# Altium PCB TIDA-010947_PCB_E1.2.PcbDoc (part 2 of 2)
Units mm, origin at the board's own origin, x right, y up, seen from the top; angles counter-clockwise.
Board outline 34 x 34 mm, 4 copper layers (Top Layer, GND, PWR, Bottom Layer), stack 1.787 mm thick; 64 components, 51 nets, 201 pads, 60 vias.
Unrouted connection lines stored in the file: 1.
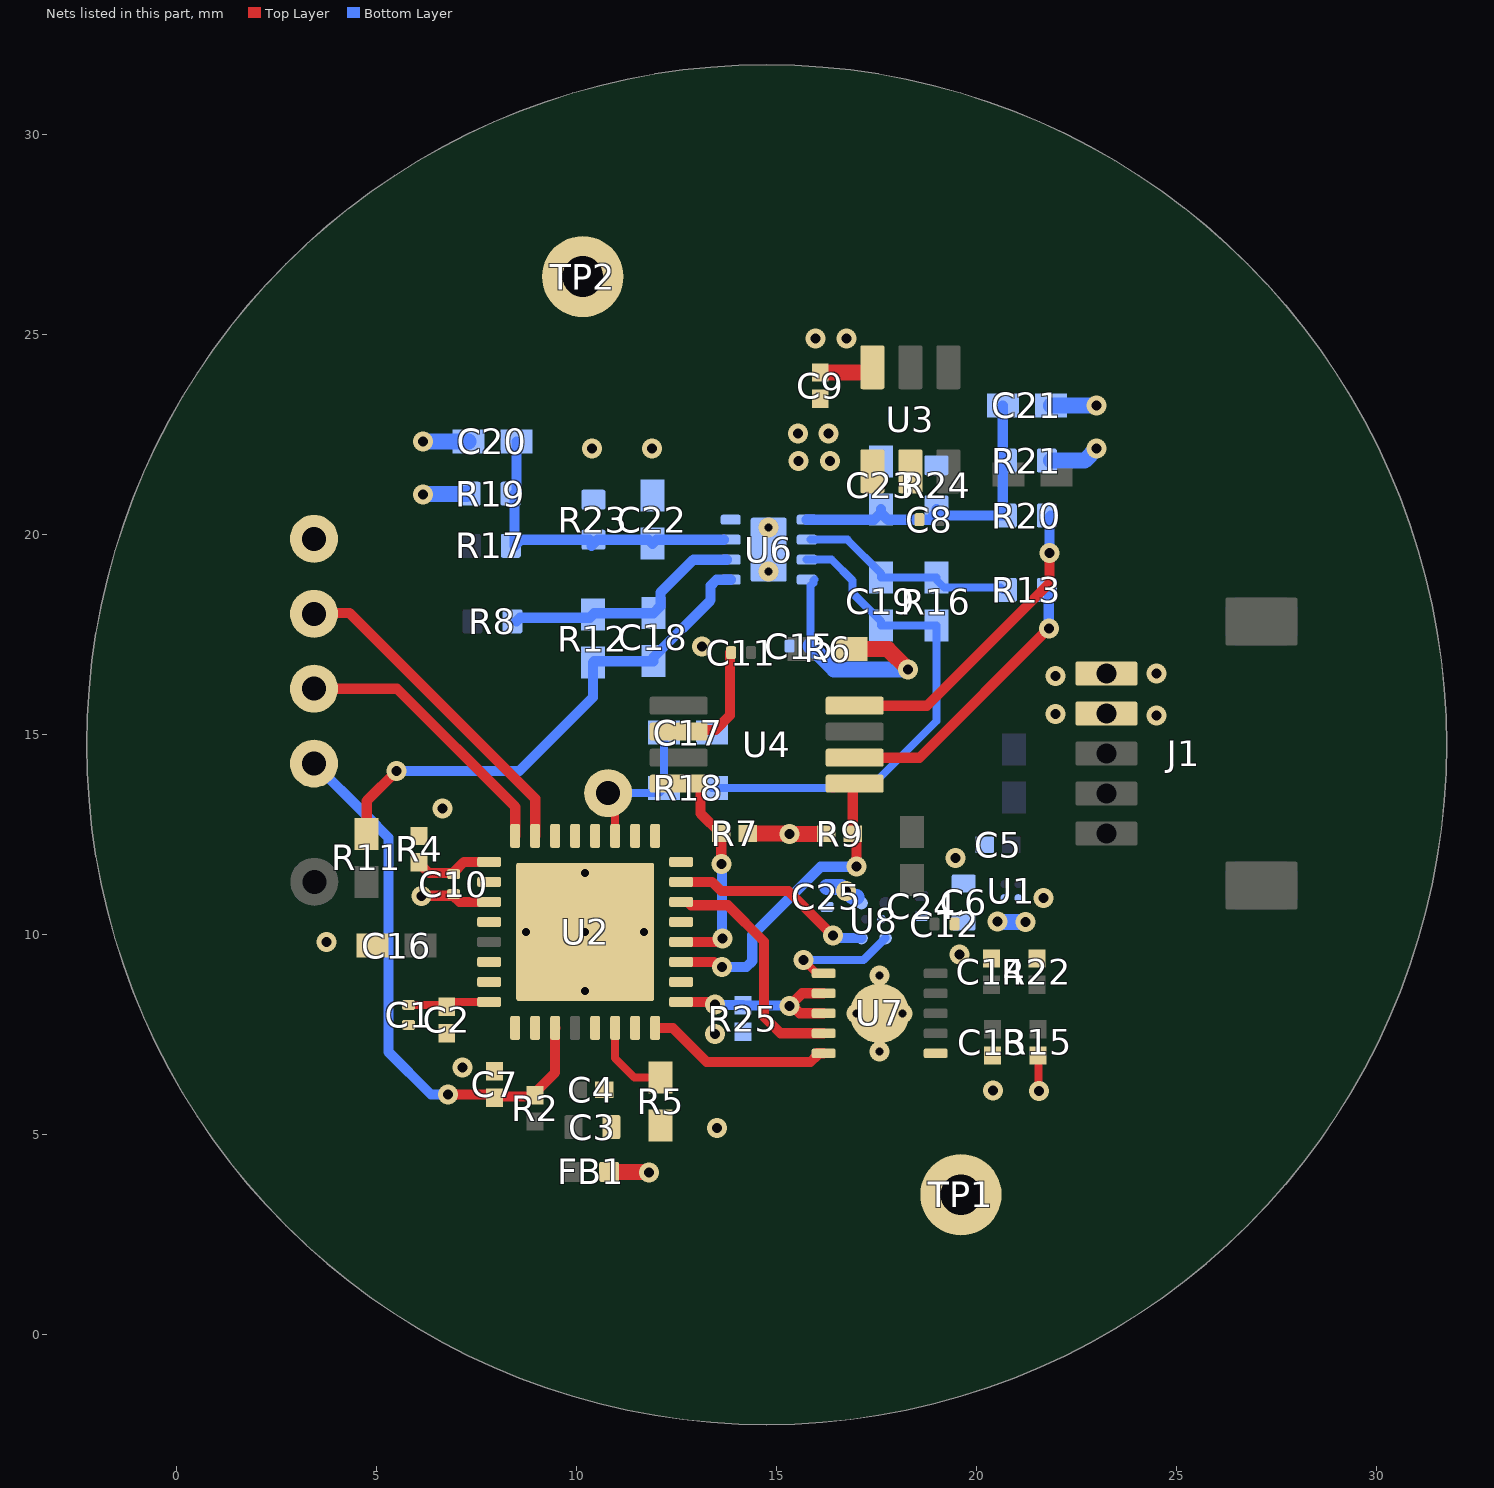
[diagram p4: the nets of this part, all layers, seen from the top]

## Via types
v1: diameter 0.5, hole 0.25, Top Layer to Bottom Layer, 49 vias
v2: diameter 0.5, hole 0.2, Top Layer to Bottom Layer, 11 vias

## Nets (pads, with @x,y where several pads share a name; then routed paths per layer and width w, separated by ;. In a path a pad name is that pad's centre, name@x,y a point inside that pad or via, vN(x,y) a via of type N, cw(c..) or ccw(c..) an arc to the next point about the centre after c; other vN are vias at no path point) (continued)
NetC18_1: C18.1 R11.1 R12.2 U6.1 | length 13
  Top Layer w0.254: R11.1@4.75,12.523 4.75,13.347 v1(5.497,14.094)
  Bottom Layer w0.254: v1(5.497,14.094) 8.566,14.094 10.404,15.931 R12.2@10.404,16.802 10.439,16.837 C18.1@11.919,16.837 11.919,16.937 13.347,18.365 13.347,18.726 13.496,18.875 U6.1@13.85,18.875
NetC18_2: C18.2 R8.2 R12.1 U6.2 | length 6.1
  Bottom Layer w0.254: R8.2@8.494,17.835 8.584,17.925 10.326,17.925 R12.1@10.404,18.002 10.439,18.037 C18.2@11.919,18.037 12.092,18.21 12.092,18.551 12.916,19.375 U6.2@13.75,19.375
NetC19_1: C19.1 R16.2 R18.1 U6.7 | length 12.8
  Bottom Layer w0.2: R18.1@13.387,13.674 17.325,13.674 18.99,15.339 R16.2@18.99,17.725 18.98,17.735 C19.1@17.605,17.735 17.605,17.835 16.895,18.545 16.895,18.855 16.375,19.375 U6.7@15.75,19.375
NetC19_2: C19.2 R13.2 R16.1 U6.6 | length 5.4
  Bottom Layer w0.2: U6.6@15.85,19.875 16.765,19.875 17.605,19.035 C19.2@17.605,18.935 18.98,18.935 R16.1@18.99,18.925 18.99,18.875 19.19,18.675 20.599,18.675 R13.2@20.652,18.622
NetC20_2: C20.2 C22.1 R17.2 R19.1 R23.2 U6.3 | length 8.2
  Bottom Layer w0.254: C20.2@8.494,22.333 8.494,21.07 8.448,21.024 8.448,19.728 8.452,19.724 8.604,19.875 10.317,19.875 R23.2@10.417,19.775 ; R23.2@10.366,19.724 R23.2@10.417,19.775 ; U6.3@13.675,19.875 11.994,19.875 C22.1@11.894,19.775 11.794,19.875 10.517,19.875 R23.2@10.417,19.775
NetC21_2: C21.2 C23.1 R20.2 R21.1 R24.2 U6.5 | length 8.1
  Bottom Layer w0.254: U6.5@15.75,20.375 17.432,20.375 C23.1@17.605,20.548 ; C23.1@17.605,20.637 C23.1@17.605,20.548 ; C21.2@20.652,23.235 20.652,21.853 20.652,20.479 19.148,20.479 18.99,20.637 18.99,20.548 18.817,20.375 17.778,20.375 C23.1@17.605,20.548
NetU7_1: U7.1 U8.3 | length 2.9
  Top Layer w0.2: v1(15.67,9.365) 15.67,9.359 15.994,9.035 U7.1@16.174,9.035
  Bottom Layer w0.2: v1(15.67,9.365) 17.17,9.365 U8.3@17.72,9.915
PA0: U2.1
PA1: U2.2
PA2: R5.2 U2.6 | length 2.1
  Top Layer w0.2: U2.6@10.962,7.67 10.954,7.663 10.954,6.913 11.443,6.424 R5.2@12.096,6.424
PA3: U2.7
PA4: U2.8 U7.5 | length 4.7
  Top Layer w0.254: U2.8@11.962,7.67 12.401,7.67 13.251,6.82 15.845,6.82 16.001,6.976 16.001,7.028 16.008,7.035 U7.5@16.174,7.035
PA5: R25.2 U2.9 U7.2 U7.3 | length 4.7
  Top Layer w0.254: U2.9@12.612,8.32 13.316,8.32 13.386,8.25 v1(13.453,8.25) ; U7.3@16.174,8.035 15.574,8.035 15.39,8.219 v1(15.324,8.219) 15.639,8.535 U7.2@16.174,8.535
  Bottom Layer w0.254: v1(13.453,8.25) 13.461,8.242 14.153,8.242 14.168,8.227 15.316,8.227 v1(15.324,8.219)
PA6: U2.10
PA7: R9.1 U2.11 U4.5 | length 8.6
  Top Layer w0.254: U2.11@12.612,9.32 13.435,9.32 13.564,9.191 v1(13.63,9.191) ; U4.5@16.401,13.677 16.499,13.775 U4.5@16.95,13.775 16.9,13.725 R9.1@16.9,12.523 16.915,12.523 16.998,12.44 v1(16.998,11.701)
  Bottom Layer w0.254: v1(13.63,9.191) 14.241,9.191 14.389,9.34 14.389,9.989 16.102,11.701 v1(16.998,11.701)
PA8: R7.1 U2.12 U4.4 | length 5.5
  Top Layer w0.254: U4.4@12.55,13.775 13.001,13.775 13.099,13.677 13.099,13.027 13.595,12.53 R7.1@13.615,12.53 v1(13.615,11.765) ; U2.12@12.785,9.82 13.503,9.82 13.583,9.9 v1(13.65,9.9)
  Bottom Layer w0.254: v1(13.615,11.765) 13.633,11.748 13.633,9.918 v1(13.65,9.9)
PA9: U2.13
PA10: U2.14 U7.4 | length 5.9
  Top Layer w0.254: U2.14@12.785,10.818 12.865,10.738 13.776,10.738 14.683,9.831 14.683,7.947 15.095,7.535 U7.4@16.174,7.535
PA11: U2.15 U8.4 | length 4.9
  Top Layer w0.254: U2.15@12.785,11.32 13.386,11.32 13.614,11.092 15.288,11.092 v1(16.405,9.975)
  Bottom Layer w0.254: v1(16.405,9.975) 16.471,9.975 16.532,9.915 U8.4@17.12,9.915
PA12: U2.16
PA13: U2.17
PA14: U2.18
PA15: C17.1 pad.8@10.784,13.541 R18.2 U2.19 | length 4
  Top Layer w0.2: pad.8@10.784,13.541 10.962,13.363 U2.19@10.962,12.47
  Bottom Layer w0.2: pad.8@10.784,13.545 12.058,13.545 R18.2@12.187,13.674 C17.1@12.187,15.054
PA16: U2.20
PA17: U2.21
PA18: U2.22
PA19: pad.8@3.432,18.024 U2.23 | length 8.4
  Top Layer w0.254: pad.8@3.441,18.035 3.458,18.046 4.317,18.046 8.962,13.401 U2.23@8.962,12.47
PA20: pad.8@3.432,16.152 U2.24 | length 7.3
  Top Layer w0.254: pad.8@3.653,15.905 3.653,15.917 3.441,16.13 3.461,16.151 5.506,16.151 8.462,13.196 U2.24@8.462,12.47
PA21: C10.2 R4.2 U2.25 | length 2
  Top Layer w0.254: R4.2@6.061,11.808 6.061,11.788 6.304,11.545 6.923,11.545 6.923,11.565 7.178,11.82 U2.25@7.812,11.82
PA22: U2.26
PA23: C9.1 C10.1 C20.1 C21.1 R19.2 R21.2 U2.27 U3.6 | length 7.8
  Top Layer w0.254: v1(6.121,10.965) 6.131,10.975 6.913,10.975 6.923,10.985 6.923,10.965 7.068,10.82 U2.27@7.812,10.82
  Top Layer w0.4: C9.1@16.09,24.056 17.29,24.056 17.39,24.156 U3.6@17.39,24.187
  Bottom Layer w0.4: v1(6.152,21.01) 6.159,21.017 7.241,21.017 R19.2@7.248,21.024 ; v1(6.152,22.333) C20.1@7.294,22.333 ; R21.2@21.852,21.853 22.695,21.853 v1(23,22.158) ; C21.1@21.852,23.235 21.853,23.236 v1(23,23.237) v1(23,23.237)
  other v1: 15.97,24.909 16.749,24.909
PA24: U2.28
PA26: U2.30
PA27: U2.31
R\S\T\: C7.1 pad.8@3.432,14.279 R2.1 U2.3 | length 13.8
  Top Layer w0.254: v1(6.776,6.004) 7.872,6.004 C7.1@7.948,5.929 7.978,5.959 8.93,5.959 R2.1@8.96,5.989 ; R2.1@9.043,6.139 9.46,6.555 9.46,7.668 U2.3@9.462,7.67
  Bottom Layer w0.254: pad.8@3.441,14.279 4.735,12.984 4.738,12.984 5.291,12.432 5.291,7.071 6.357,6.004 v1(6.776,6.004)
SIN_N: R13.1 U4.6 | length 7.2
  Top Layer w0.254: U4.6@16.95,14.425 18.569,14.425 v1(21.802,17.658)
  Bottom Layer w0.254: v1(21.802,17.658) 21.802,18.572 R13.1@21.852,18.622
SIN_P: R20.1 U4.8 | length 7.8
  Top Layer w0.254: U4.8@16.95,15.725 18.759,15.725 21.816,18.782 v1(21.816,19.544)
  Bottom Layer w0.254: v1(21.816,19.544) 21.816,20.442 R20.1@21.852,20.479
TPAD: C1.2 C2.1 C3.2 C4.1 C5.2 C6.1 C7.2 C8.1 C9.2 C11.1 C12.1 C13.1 C14.2 C15.1 C16.2 C17.2 C22.2 C23.2 C24.1 C25.1 J1.4 J1.5 pad.8@3.432,19.897 pad.9 pad.10 R4.1 R5.1 R22.1 R23.1 R24.1 R25.1 TP1.1 TP2.1 U1.B2 U2.5 U2.33 U3.1 U3.2 U4.2 U6.4 U6.9@14.8,19.625 U7.6 U7.11 U8.2 | length 3
  Top Layer w0.254: U4.2@12.55,15.075 12.59,15.115 13.462,15.115 13.83,15.483 C11.1@13.83,17.052
  other v1: 13.51,5.171 20.413,6.103 7.149,6.675 13.461,7.52 19.576,9.506 3.75,9.82 21.669,10.913 19.475,11.923 6.644,13.153 24.5,15.484 21.965,15.514 21.965,16.473 24.5,16.53 13.135,17.202 15.544,21.845 16.329,21.845 10.387,22.159 11.881,22.159 15.537,22.537 16.3,22.532
  other v2: 17.574,7.085 16.999,8.035 18.149,8.035 10.212,8.595 17.574,8.985 8.737,10.07 10.212,10.07 11.687,10.07 10.212,11.545 14.8,19.075 14.8,20.175
VCORE: C1.1 C2.2 U2.32 | length 2.1
  Top Layer w0.2: C1.1@5.797,8.246 6.705,8.246 C2.2@6.749,8.201 6.749,8.21 6.859,8.32 U2.32@7.812,8.32
VDD_3V3: C6.2 C15.2 C25.2 FB1.2 R6.1 R7.2 R9.2 R15.2 U1.A2 U6.8 U8.6 | length 11.4
  Top Layer w0.2: R15.2@21.53,6.98 21.542,6.968 21.542,6.103 v1(21.554,6.09)
  Top Layer w0.4: FB1.2@10.812,4.07 10.818,4.064 11.795,4.064 v1(11.802,4.058) ; R7.2@14.275,12.53 14.278,12.527 15.32,12.527 v1(15.324,12.523) R9.2@16.24,12.523 ; R6.1@16.87,17.137 17.776,17.137 v1(18.283,16.63)
  Bottom Layer w0.2: C15.2@15.85,17.218 15.85,18.733 15.915,18.798 15.915,18.852 U6.8@15.939,18.875
  Bottom Layer w0.4: C15.2@15.85,17.218 16.438,16.63 v1(18.283,16.63) ; C25.2@16.255,11.195 16.605,11.195 16.708,11.092 v1(16.735,11.092) 16.762,11.092 16.914,10.94 16.995,10.94 ; v1(20.514,10.325) 20.516,10.323 21.217,10.323 v1(21.22,10.32)
pads on no net: J1.MP1 J1.MP2 U3.5 U6.9@14.8,19.175 U6.9@14.8,20.075 U7.7

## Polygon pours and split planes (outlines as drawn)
TPAD on Bottom Layer "BOTTOM_LAYER_TPAD_P050" (solid, pour order 50): -2.25,31.75 31.75,31.75 31.75,-2.25 -2.25,-2.25
VDD_3V3 on Bottom Layer "BOTTOM_LAYER_VDD_3V3_P014" (solid, pour order 14): 20.514,11.018 20.849,11.018 20.849,10.63 20.849,10.02 19.552,10.02 19.502,10.07 19.502,10.808 20.444,10.808 20.514,10.878
NetC5_1 on Bottom Layer "BOTTOM_LAYER_NETC5_1_P017" (solid, pour order 17): 20.514,13.93 20.514,11.162 21.284,11.162 21.284,13.93
TPAD on Top Layer "TOP_LAYER_TPAD_P045" (solid, pour order 45): -2.25,31.75 31.75,31.75 31.75,-2.25 -2.25,-2.25
MCU_3V3 on Top Layer "TOP_LAYER_MCU_3V3_P029" (solid, pour order 29): 10.362,6.289 10.362,3.795 8.877,3.795 8.667,4.006 8.667,5.654 9.18,5.654 9.815,6.289
NetC8_2 on Top Layer "TOP_LAYER_NETC8_2_P015" (solid, pour order 15): 18.99,24.75 18.99,20.889 18.88,20.779 18.88,20.205 19.994,20.205 20.989,21.2 21.234,21.2 21.234,24.638 21.122,24.75
5V on Top Layer "TOP_LAYER_5V_P016" (solid, pour order 16): 22.472,14.208 25.864,14.208 25.864,21.805 21.602,21.805 21.602,21.249 21.554,21.2 25.056,21.2 25.056,15 22.472,15
PA23 on Top Layer "TOP_LAYER_PA23_P023" (solid, pour order 23): 15.614,25.18 15.614,23.824 16.964,23.824 17.085,23.704 17.69,23.704 17.69,25.12 17.631,25.18
TPAD on PWR "PWR_TPAD_P047" (solid, pour order 47): -2.25,31.75 31.75,31.75 31.75,-2.25 -2.25,-2.25
VDD_3V3 on PWR "PWR_VDD_3V3_P044" (solid, pour order 44): 14.382,12.699 15.97,11.111 17.061,10.02 20.772,10.02 20.772,12.736 20.728,12.78
VDD_3V3 on PWR "PWR_VDD_3V3_P018" (solid, pour order 18): 20.849,10.02 19.552,10.02 19.552,15.905 19.091,16.366 17.896,16.366 17.896,17.047 18.051,17.202 20.795,17.202 20.795,10.075
PA23 on PWR "PWR_PA23_P022" (solid, pour order 22): 22.296,21.853 22.313,21.837 24,21.837 24,25 23.82,25.18 6.871,25.18 5.565,23.874 5.565,10.925 6.047,10.443 6.776,10.443 6.776,22.676 7.804,23.704 21.837,23.704 22.296,23.244
VDD_3V3 on PWR "PWR_VDD_3V3_P032" (solid, pour order 32): 20.135,10.713 21.815,10.713 21.965,10.563 21.94,10.538 21.94,5.274 13.655,5.274 11.881,3.5 11.398,3.5 11.398,4.654 13.135,6.39 19.527,6.39 20.135,6.998
TPAD on GND "GND_TPAD_P046" (solid, pour order 46): -2.25,31.75 31.75,31.75 31.75,-2.25 -2.25,-2.25

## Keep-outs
Keep-Out Layer:
  text ".Layer_Name" at 14.656,-21.806 h0.9

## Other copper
Top Layer:
  text ".Layer_Name" at 14.656,-21.806 h0.9
Bottom Layer:
  text ".Layer_Name" at 14.656,-21.806 h0.9

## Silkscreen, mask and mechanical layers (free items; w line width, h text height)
Top Overlay:
  lines w0.254: 4.251,13.416 2.5,13.416 2.5,20.834 4.263,20.834 4.263,13.429
  text "4-GND / 3-DIO / 2-CLK / 1-RST" at -1,16.537 h1.2
  text "5-GND / 4-GND / 3-5V / 2-B / 1-A" at 26.243,5.483 h1.2
  text ".Layer_Name" at 14.656,-21.806 h0.9
Bottom Overlay:
  text "4-GND / 3-DIO / 2-CLK / 1-RST" at 2.25,16.473 h1.2
  text "5-GND / 4-GND / 3-5V / 2-B / 1-A" at 27.874,5.468 h1.2
  text ".Layer_Name" at 14.656,-21.806 h0.9
Top Paste:
  text ".Layer_Name" at 14.656,-21.806 h0.9
Bottom Paste:
  text ".Layer_Name" at 14.656,-21.806 h0.9
Top Solder:
  text ".Layer_Name" at 14.656,-21.806 h0.9
  text ".Layer_Name" at 14.656,-21.806 h0.9
Bottom Solder:
  text ".Layer_Name" at 14.656,-21.806 h0.9
Drill Guide:
  text ".Layer_Name" at 14.656,-21.806 h0.9
M1 Board Outline:
  circle w0.254: c29.5,14.75 r1
  circle w0.254: c0,14.75 r1
  circle w0.254: c4.32,4.32 r1.2
  circle w0.254: c25.18,25.18 r1.2
  circle w0.254: c14.75,29.5 r1
  circle w0.254: c4.32,25.18 r1.2
  circle w0.254: c14.75,0 r1
  circle w0.254: c25.18,4.32 r1.2
  circle w0.254: c14.75,14.75 r17
  text ".Layer_Name" at 14.656,-21.806 h0.9
M2 Board Dimensions:
  rectangle: 0,-6.985 3.175,-3.81
  rectangle: 3.175,-10.16 12.7,-6.985
  lines w0.178: 0,-6.985 25.4,-6.985 ; 3.175,-10.16 3.175,-3.81 ; 6.35,-10.16 6.35,-3.81 ; 12.7,-10.16 12.7,-3.81 ; 19.05,-10.16 19.05,-3.81 ; 0,-10.16 25.4,-10.16 25.4,-3.81 0,-3.81 0,-10.16
  text ".Layer_Name" at 14.656,-21.806 h0.9
M3 3D STEP Top:
  text ".Layer_Name" at 14.656,-21.806 h0.9
M4 3D STEP Bottom:
  text ".Layer_Name" at 14.656,-21.806 h0.9
M5 Assembly Top:
  lines w0.254: -7.417,-23.626 160.223,-23.626 ; -7.417,-18.462 160.274,-18.462 ; -7.417,-13.297 -7.417,-28.791 94.31,-28.791 160.274,-28.791 160.274,-13.297 -7.404,-13.297 -7.404,-28.791 32.614,-28.791 ; 55.194,-28.791 55.194,-13.297 ; 87.376,-18.462 87.376,-13.297 ; 108.712,-18.462 108.712,-13.297 ; 124.511,-28.956 124.511,-23.804
  text "COMPONENTS MARKED 'DNP' SHOULD NOT BE POPULATED." at 29.299,-8.09 h1.02
  text "ASSEMBLY VARIANT:" at 29.286,-11.024 h1.02
  text ".VariantName" at 55.601,-11.024 h1.02
  text "PCB VIEWED FROM TOP SIDE" at -5.804,-16.654 h0.9
  text "BOARD #:" at 57.099,-16.654 h0.9
  text ".PRJ_Number" at 70.955,-16.654 h0.9
  text "REV:" at 92.405,-16.654 h0.9
  text ".PCB_Rev" at 99.809,-16.654 h0.9
  text "SVN REV:" at 113.69,-16.654 h0.9
  text ".VersionControl_RevNumber" at 126.543,-16.654 h0.9
  text "TID #:" at 57.099,-21.819 h0.9
  text ".TID" at 70.955,-21.819 h0.9
  text "PLOT NAME =" at -5.804,-27.034 h0.9
  text ".plot_File_Name" at 14.656,-27.034 h0.9
  text "GENERATED    :" at 57.15,-27.034 h0.9
  text ".Print_Date" at 79.235,-27.034 h0.9
  text ".Print_Time" at 97.752,-27.034 h0.9
  text "TEXAS INSTRUMENTS" at 129.87,-27.034 h0.9
M6 Assembly Bottom:
  lines w0.254: -7.429,-18.474 160.261,-18.474 ; -7.379,-23.639 160.261,-23.639 ; 28.334,-28.969 28.334,-23.817 ; 44.133,-18.474 44.133,-13.31 ; 65.468,-18.474 65.468,-13.31 ; 97.65,-28.804 97.65,-13.31 ; 120.231,-28.804 160.249,-28.804 160.249,-13.31 -7.429,-13.31 -7.429,-28.804 58.534,-28.804 160.261,-28.804 160.261,-13.31
  text "COMPONENTS MARKED 'DNP' SHOULD NOT BE POPULATED." at 154.991,-8.077 h1.02
  text ".VariantName" at 128.473,-11.024 h1.02
  text "ASSEMBLY VARIANT:" at 154.864,-11.024 h1.02
  text ".VersionControl_RevNumber" at 26.302,-16.667 h0.9
  text "SVN REV:" at 39.154,-16.667 h0.9
  text ".PCB_Rev" at 53.035,-16.667 h0.9
  text "REV:" at 60.439,-16.667 h0.9
  text ".PRJ_Number" at 81.89,-16.667 h0.9
  text "BOARD #:" at 95.745,-16.667 h0.9
  text "PCB VIEWED FROM BOTTOM SIDE" at 158.648,-16.667 h0.9
  text ".TID" at 81.89,-21.831 h0.9
  text "TID #:" at 95.745,-21.831 h0.9
  text "TEXAS INSTRUMENTS" at 22.974,-27.047 h0.9
  text ".Print_Time" at 55.093,-27.047 h0.9
  text ".Print_Date" at 73.609,-27.047 h0.9
  text "GENERATED    :" at 95.694,-27.047 h0.9
  text ".plot_File_Name" at 138.189,-27.047 h0.9
  text "PLOT NAME =" at 158.648,-27.047 h0.9
M9 Title Sheet:
  drawing of 57 lines, arcs and shapes, not listed
  text "1" at 18.792,204.127 h1.78
  text "2" at 82.182,204.127 h1.78
  text "3" at 145.411,204.127 h1.78
  text "4" at 209.08,204.127 h1.78
  text "5" at 272.555,204.127 h1.78
  text "6" at 336.182,204.127 h1.78
  text "A" at -10.579,175.095 h1.78
  text "A" at 365.341,175.095 h1.78
  text "B" at -10.579,114.643 h1.78
  text "B" at 365.341,114.643 h1.78
  text "C" at -10.579,54.318 h1.78
  text "C" at 365.341,54.318 h1.78
  text "PROJECT TITLE:" at 288.125,7.048 h1.14
  text ".PRJ_Title" at 289.395,3.662 h1.78
  text "DESIGNED FOR:" at 288.125,-0.597 h1.14
  text ".PRJ_Customer" at 289.395,-4.153 h1.78
  text "D" at -10.579,-5.88 h1.78
  text "D" at 365.341,-5.88 h1.78
  text "FILE NAME:" at 288.125,-8.217 h1.14
  text ".PCB_File_Name_No_Path" at 289.395,-11.265 h1.78
  text "Texas Instruments (TI) and/or its licensors do not warrant the accuracy or completeness of this specification" at 161.9,-15.376 h1.14
  text "ENGINEER:" at 288.125,-15.583 h1.14
  text "LAYOUT BY:" at 326.352,-15.583 h1.14
  text "or any information contained therein. TI and/or its licensors do not warrant that this design will meet" at 160.757,-18.237 h1.14
  text ".PRJ_Engineer" at 289.395,-19.52 h1.78
  text ".PCB_Layout" at 327.635,-19.52 h1.78
  text "the specifications, will be suitable for your application or fit for any particular purpose, or will operate in" at 160.757,-21.099 h1.14
  text ".Layer_Name" at 14.656,-21.806 h0.9
  text "ALTIUM DESIGNER VERSION:" at 326.352,-23.457 h1.14
  text "an implementation. TI and/or its licensors do not warrant that the design is production worthy. You should" at 160.757,-23.961 h1.14
  text "completely validate and test your design implementation to confirm the system functionality for your application." at 161.9,-26.822 h1.14
  text ".print_Scale" at 289.395,-26.843 h1.78
  text ".Application_BuildNumber" at 327.635,-26.843 h1.78
  text "1" at 18.792,-32.093 h1.78
  text "2" at 82.182,-32.093 h1.78
  text "3" at 145.411,-32.093 h1.78
  text "4" at 209.08,-32.093 h1.78
  text "5" at 272.555,-32.093 h1.78
  text "6" at 336.182,-32.093 h1.78
M10 Fab Notes:
  drawing of 189 lines, arcs and shapes, not listed
  text "DESIGN INFORMATION" at 314.503,161.447 h0.9
  text "MIN. TRACK WIDTH:" at 298.131,158.091 h0.9
  text "8" at 325.976,158.091 h0.9
  text "MIL" at 329.907,158.091 h0.9
  text "7.874" at 321.75,155 h0.9
  text "MIN. CLEARANCE:" at 298.131,154.938 h0.9
  text "MIL" at 329.907,154.938 h0.9
  text "MIN. VIA PAD SIZE:" at 298.131,151.785 h0.9
  text "24" at 325.214,151.785 h0.9
  text "MIL" at 329.907,151.785 h0.9
  text "0.05mm (2MIL)" at 315.784,148.486 h0.9
  text "MINIMUM ANNULAR RING" at 289.769,148.277 h0.9
  text "EXTERNAL" at 333.768,148.277 h0.9
  text "PER" at 294.849,145.48 h0.9
  text "IPC-D-275 CLASS 2 LEVEL C" at 300.437,145.48 h0.9
  text "MIL, HOLES" at 338.238,142.928 h0.9
  text "+/-" at 328.27,142.709 h0.9
  text "+/-" at 349.961,142.709 h0.9
  text "REGISTRATION TOLERANCES:" at 289.769,142.682 h0.9
  text "METAL" at 320.243,142.682 h0.9
  text "5" at 334.879,142.683 h0.9
  text "3" at 356.037,142.683 h0.9
  text "MIL" at 358.99,142.682 h0.9
  text "HOLE SIZE TOLERANCE (UNLESS OTHERWISE SPECIFIED):" at 289.769,140.185 h0.9
  text "+/-" at 349.961,140.112 h0.9
  text "3" at 356.037,140.085 h0.9
  text "MIL" at 358.99,140.085 h0.9
  text "MATERIAL:" at 287.87,136.589 h0.9
  text "FR-4 High Tg" at 312.926,133.324 h0.9
  text "X" at 309.257,133.122 h0.9
  text "FR-4" at 298.563,133.007 h0.9
  text "OTHER" at 336.358,133.007 h0.9
  text "62 MIL (1.6mm) +/-10%" at 306.694,129.374 h0.9
  text "X" at 303.643,129.312 h0.9
  text "THICKNESS:" at 289.769,129.165 h0.9
  text "OTHER" at 339.33,129.165 h0.9
  text "TOLERANCE:" at 289.769,125.652 h0.9
  text "X" at 311.314,125.652 h0.9
  text "ANSI IPC-6012 TYPE 3 CLASS 2" at 315.836,125.652 h0.9
  text "OTHER +/-" at 315.835,121.989 h0.9
  text "BOW & TWIST:" at 289.769,118.302 h0.9
  text "X" at 311.314,118.302 h0.9
  text "ANSI IPC-6012 TYPE 3 CLASS 2" at 315.836,118.302 h0.9
  text "OTHER +/-" at 315.835,114.576 h0.9
  text "DRILLING:" at 287.87,111.258 h0.9
  text "NC_DRILL FILES" at 332.599,108.586 h0.9
  text "REFERENCE:" at 289.769,108.486 h0.9
  text "X" at 306.463,108.484 h0.9
  text "AS SHOWN" at 310.984,108.486 h0.9
  text "X" at 329.348,108.486 h0.9
  text "OTHER" at 340.168,104.873 h0.9
  text "PTH COPPER THICKNESS:" at 289.761,104.783 h0.9
  text "X" at 318.697,104.783 h0.9
  text "20-30 um" at 321.948,104.783 h0.9
  text "BOARD FINISH:" at 287.87,101.034 h0.9
  text "SILKSCREEN:" at 291.812,98.237 h0.9
  text "X" at 316.14,98.237 h0.9
  text "TOP" at 319.112,98.237 h0.9
  text "X" at 329.094,98.237 h0.9
  text "BOTTOM" at 332.091,98.237 h0.9
  text "SILKSCREEN COLOR:" at 291.812,94.295 h0.9
  text "X" at 316.115,94.295 h0.9
  text "WHITE" at 319.112,94.295 h0.9
  text "OTHER" at 332.091,94.295 h0.9
  text "X" at 319.442,90.652 h0.9
  text "GREEN" at 322.439,90.652 h0.9
  text "OTHER" at 338.136,90.652 h0.9
  text "SOLDER RESIST COLOR:" at 291.812,90.477 h0.9
  text "X" at 319.442,86.734 h0.9
  text "MATTE" at 322.439,86.734 h0.9
  text "SEMI-GLOSS" at 338.125,86.717 h0.9
  text "IMMERSION GOLD (ENIG)" at 314.819,82.345 h0.9
  text "ENEPIG" at 348.793,82.162 h0.9
  text "SURFACE FINISH:" at 287.87,82.136 h0.9
  text "X" at 310.298,82.136 h0.9
  text "IMM. TIN/SILVER OR EQUIV" at 296.24,78.649 h0.9
  text "OTHER" at 332.599,78.549 h0.9
  text "ARRAY/PANEL:" at 287.87,74.602 h0.9
  text "CUT AND TRIM PER M1 BOARD OUTLINE" at 314.819,74.393 h0.9
  text "N.C. ROUTE" at 314.819,70.94 h0.9
  text "X" at 332.295,70.94 h0.9
  text "V. SCORE" at 336.816,70.94 h0.9
  text "CERTIFICATION:" at 287.87,67.66 h0.9
  text "MATERIALS AND WORKMANSHIP FOR ALL PCBS" at 306.285,67.66 h0.9
  text "TO MEET OR EXCEED THE REQUIREMENTS OF:" at 306.285,65.271 h0.9
  text "X" at 297.078,62.003 h0.9
  text "ANSI IPC-A-600F CLASS ->" at 300.329,62.003 h0.9
  text "X" at 342.188,62.003 h0.9
  text "2" at 344.982,62.003 h0.9
  text "1" at 336.981,61.965 h0.9
  text "3" at 353.973,61.965 h0.9
  text "X" at 317.702,58.252 h0.9
  text "RoHS" at 320.953,58.252 h0.9
  text "OTHER" at 337.321,58.252 h0.9
  text "PER ORDER" at 347.407,58.252 h0.9
  text "ALL BOARDS MUST MEET OR EXCEED UL94-V0 REQUIREMENTS." at 288.569,54.345 h0.9
  text "PCB MUST BEAR THE UL94V-0 UL REGISTERED MATERIAL ID NUMBER" at 288.569,51.397 h0.9
  text "ADDITIONAL REQUIREMENTS:" at 287.87,47.094 h0.9
  text "MICROSECTION:" at 289.769,44.373 h0.9
  text "YES" at 312.775,44.373 h0.9
  text "REQUIRED" at 334.657,40.707 h0.9
  text "BARE BOARD ELEC. TEST:" at 289.769,40.634 h0.9
  text "NONE" at 322.935,40.634 h0.9
  text "X" at 331.66,40.634 h0.9
  text "PER ORDER" at 349.693,40.634 h0.9
  text "XX MIL VIAS REQUIRE NON-CONDUCTIVE FILL AND PLANARIZE" at 294.04,35.428 h1.5
  text "XX MIL VIAS REQUIRE CONDUCTIVE FILL AND PLANARIZE" at 294.243,32.787 h0.9
  text "OUTER XX MIL TRACES REQUIRE 50 OHM SINGLE-ENDED IMPEDANCE" at 294.218,28.637 h1.47
  text "LAYER 2 & 3 (INNER LAYERS) XX MIL WIDE, XX MIL SPACE / TRACES REQUIRE 100 OHM DIFFERENTIAL IMPEDANCE" at 294.015,22.65 h0.9
  text ".Layer_Name" at 14.656,-21.806 h0.9
M11 Gerber Information:
  lines w0.254: -7.417,-23.626 160.223,-23.626 ; -7.417,-18.462 160.274,-18.462 ; -7.417,-13.297 -7.417,-28.791 94.31,-28.791 160.274,-28.791 160.274,-13.297 -7.404,-13.297 -7.404,-28.791 32.614,-28.791 ; 55.194,-28.791 55.194,-13.297 ; 87.376,-18.462 87.376,-13.297 ; 108.712,-18.462 108.712,-13.297 ; 124.511,-28.956 124.511,-23.804
  text "ALL ARTWORK VIEWED FROM TOP SIDE" at -5.804,-16.654 h0.9
  text "BOARD #:" at 57.099,-16.654 h0.9
  text ".PRJ_Number" at 70.955,-16.654 h0.9
  text "REV:" at 92.405,-16.654 h0.9
  text ".PCB_Rev" at 99.809,-16.654 h0.9
  text "SVN REV:" at 113.69,-16.654 h0.9
  text ".VersionControl_RevNumber" at 126.543,-16.654 h0.9
  text "LAYER NAME =" at -5.804,-21.806 h0.9
  text "TID #:" at 57.099,-21.819 h0.9
  text ".TID" at 70.955,-21.819 h0.9
  text "PLOT NAME =" at -5.804,-27.034 h0.9
  text ".plot_File_Name" at 14.656,-27.034 h0.9
  text "GENERATED    :" at 57.15,-27.034 h0.9
  text ".Print_Date" at 79.235,-27.034 h0.9
  text ".Print_Time" at 97.752,-27.034 h0.9
  text "TEXAS INSTRUMENTS" at 129.87,-27.034 h0.9
M12 Stackup:
  drawing of 196 lines, arcs and shapes, not listed
  text "Layer" at 248.707,200.785 h1.02
  text "Name" at 252.958,200.785 h1.02
  text "Material" at 261.181,200.785 h1.02
  text "Thickness" at 268.57,200.785 h1.02
  text "Constant" at 274.639,200.785 h1.02
  text "Board Layer Stack" at 280.256,200.785 h1.02
  text "Top Overlay" at 252.958,198.753 h1.02
  text "Top Solder" at 252.958,196.721 h1.02
  text "Solder Resist" at 261.181,196.721 h1.02
  text "0.40mil" at 268.57,196.721 h1.02
  text "3.5" at 274.639,196.721 h1.02
  text "1" at 248.707,194.689 h1.02
  text "Top Layer" at 252.958,194.689 h1.02
  text "1.40mil" at 268.57,194.689 h1.02
  text "Dielectric 1" at 252.958,192.657 h1.02
  text "PP-006" at 261.181,192.657 h1.02
  text "2.80mil" at 268.569,192.657 h1.02
  text "4.1" at 274.639,192.657 h1.02
  text "2" at 248.706,190.625 h1.02
  text "GND" at 252.958,190.625 h1.02
  text "CF-004" at 261.181,190.625 h1.02
  text "1.38mil" at 268.57,190.625 h1.02
  text "Dielectric1" at 252.958,188.593 h1.02
  text "FR-4 High Tg" at 261.181,188.593 h1.02
  text "59.20mil" at 268.57,188.593 h1.02
  text "4.8" at 274.639,188.593 h1.02
  text "3" at 248.707,186.561 h1.02
  text "PWR" at 252.958,186.561 h1.02
  text "CF-004" at 261.181,186.561 h1.02
  text "1.38mil" at 268.57,186.561 h1.02
  text "Dielectric 2" at 252.958,184.529 h1.02
  text "PP-006" at 261.181,184.529 h1.02
  text "2.80mil" at 268.569,184.529 h1.02
  text "4.1" at 274.639,184.529 h1.02
  text "4" at 248.707,182.497 h1.02
  text "Bottom Layer" at 252.958,182.497 h1.02
  text "1.40mil" at 268.57,182.497 h1.02
  text "Bottom Solder" at 252.958,180.465 h1.02
  text "Solder Resist" at 261.181,180.465 h1.02
  text "0.40mil" at 268.57,180.465 h1.02
  text "3.5" at 274.639,180.465 h1.02
  text "Bottom Overlay" at 252.958,178.433 h1.02
  text ".Layer_Name" at 14.656,-21.806 h0.9
M13 Component Bodies Top:
  text ".Layer_Name" at 14.656,-21.806 h0.9
M14 Component Bodies Bottom:
  text ".Layer_Name" at 14.656,-21.806 h0.9
M15 Courtyards Top:
  text ".Layer_Name" at 14.656,-21.806 h0.9
M16 Courtyards Bottom:
  text ".Layer_Name" at 14.656,-21.806 h0.9
Drill Drawing:
  circle w0.254: c135.607,83.024 r0.468
  lines w0.254: 135.139,76.474 135.373,76.474 135.607,76.24 135.841,76.474 136.075,76.474 135.841,76.708 136.075,76.942 135.841,76.942 135.607,77.176 135.373,76.942 135.139,76.942 135.373,76.708 135.139,76.474 ; 135.139,79.281 136.075,79.281 135.607,78.345 135.139,79.281 ; 135.139,80.684 135.373,80.684 135.373,80.451 135.841,80.451 135.841,80.684 136.075,80.684 136.075,81.152 135.841,81.152 135.841,81.386 135.373,81.386 135.373,81.152 135.139,81.152 135.139,80.684 ; 135.139,84.661 136.075,84.661 136.075,85.596 135.139,85.596 135.139,84.661
  lines w0.305: 134.264,75.609 188.984,75.609 ; 134.264,86.134 188.984,86.134 ; 139.986,73.504 139.986,88.24 ; 145.607,73.504 145.607,88.24 ; 156.387,73.504 156.387,88.24 ; 160.775,73.504 160.775,88.24 ; 167.127,73.504 167.127,88.24 ; 179.393,73.504 179.393,88.24 ; 134.264,73.504 188.984,73.504 188.984,88.24 134.264,88.24 134.264,73.504
  text "Symbol" at 135.527,86.766 h1.22
  text "Quantity" at 140.617,86.766 h1.22
  text "Finished Hole Size" at 146.239,86.766 h1.22
  text "Plated" at 157.018,86.766 h1.22
  text "Hole Type" at 161.406,86.766 h1.22
  text "Drill Layer Pair" at 167.759,86.766 h1.22
  text "Hole Tolerance" at 180.024,86.766 h1.22
  text "11" at 140.617,84.661 h1.02
  text "7.87mil (0.200mm)" at 146.239,84.661 h1.02
  text "PTH" at 157.018,84.661 h1.02
  text "Round" at 161.406,84.661 h1.02
  text "Top Layer - Bottom Layer" at 167.759,84.661 h1.02
  text "49" at 140.617,82.556 h1.02
  text "9.84mil (0.250mm)" at 146.239,82.556 h1.02
  text "PTH" at 157.018,82.556 h1.02
  text "Round" at 161.406,82.556 h1.02
  text "Top Layer - Bottom Layer" at 167.759,82.556 h1.02
  text "5" at 140.617,80.451 h1.02
  text "19.69mil (0.500mm)" at 146.239,80.451 h1.02
  text "PTH" at 157.018,80.451 h1.02
  text "Round" at 161.406,80.451 h1.02
  text "Top Layer - Bottom Layer" at 167.759,80.451 h1.02
  text "6" at 140.617,78.345 h1.02
  text "23.62mil (0.600mm)" at 146.239,78.345 h1.02
  text "PTH" at 157.018,78.345 h1.02
  text "Round" at 161.406,78.345 h1.02
  text "Top Layer - Bottom Layer" at 167.759,78.345 h1.02
  text "2" at 140.617,76.24 h1.02
  text "40.00mil (1.016mm)" at 146.239,76.24 h1.02
  text "PTH" at 157.018,76.24 h1.02
  text "Round" at 161.406,76.24 h1.02
  text "Top Layer - Bottom Layer" at 167.759,76.24 h1.02
  text "73 Total" at 140.617,74.135 h1.02
  text ".Layer_Name" at 14.656,-21.806 h0.9
M17 Embedded Cavity:
  text ".Layer_Name" at 14.656,-21.806 h0.9
M18 Embedded Assembly:
  text ".Layer_Name" at 14.656,-21.806 h0.9
M19 Embedded Keepout:
  text ".Layer_Name" at 14.656,-21.806 h0.9

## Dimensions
0,-10.16 to 25.4,-10.16 on M2 Board Dimensions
